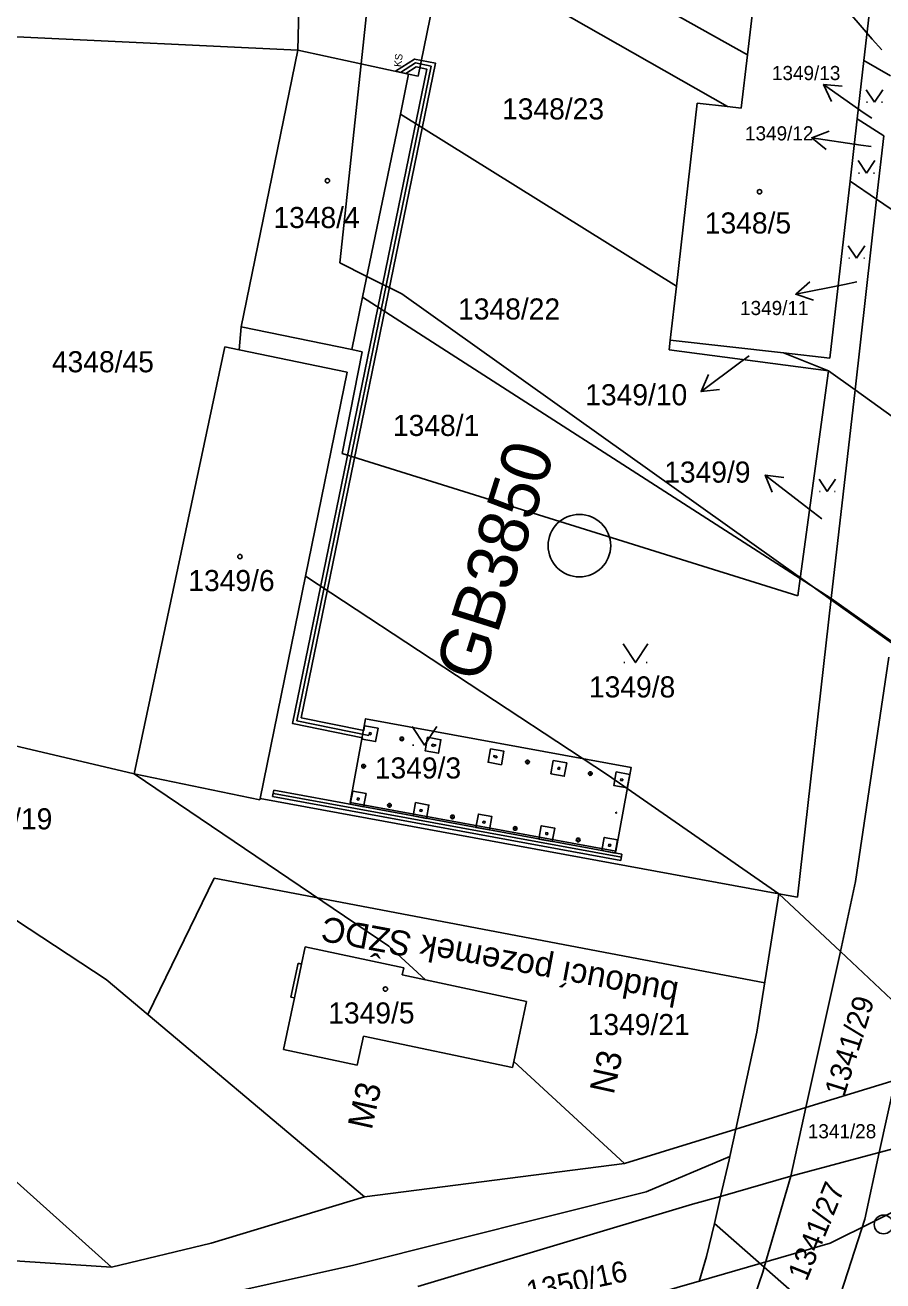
# Model space of a CAD drawing. Extents: x -735036 to -734743, y -1144813 to -1144181.
# Drawn here: x -734915.4 to -734846.3, y -1144707.5 to -1144606.3 of the extents above; entities that cross this region are included whole.
import ezdxf

# ---------------------------------------------------------------- set-up
doc = ezdxf.new("R2010")
doc.units = 0
for name, color, linetype in [('A3_ODVODŇOVACÍ ŽLAB', 7, 'Continuous'), ('A3_SIT_OBJEKT_N', 7, 'Continuous'), ('A3_SIT_OBJEKTY_N01', 7, 'Continuous'), ('BPEJ', 7, 'Continuous'), ('CKEL_VEDENI_NN_PODZ_N', 7, 'Continuous'), ('CKTEXTY_MALE', 7, 'Continuous'), ('hranice pl. určené SŽDC', 7, 'Continuous'), ('Katastr_HRANICE DRÁHY', 7, 'Continuous'), ('Katastr_Hranice parcel', 7, 'Continuous'), ('Katastr_Parcelní čísla', 7, 'Continuous'), ('Katastr_Slučkované čáry', 7, 'Continuous'), ('Katastr_Značky kultur', 7, 'Continuous'), ('ŽBP', 7, 'Continuous')]:
    doc.layers.add(name, color=color, linetype=linetype)

msp = doc.modelspace()

# ---------------------------------------------------------------- linework, layer by layer
at = {"layer": 'A3_ODVODŇOVACÍ ŽLAB'}
msp.add_line((-734867.33, -1144673.4), (-734895.36, -1144668.25), dxfattribs=at)
at = {"layer": 'A3_SIT_OBJEKT_N'}
for p, q in [((-734895.42, -1144668.49), (-734895.31, -1144668)), ((-734867.38, -1144673.65), (-734895.42, -1144668.49)), ((-734895.31, -1144668), (-734867.29, -1144673.15)), ((-734867.29, -1144673.15), (-734867.38, -1144673.65))]:
    msp.add_line(p, q, dxfattribs=at)
at = {"layer": 'A3_SIT_OBJEKTY_N01'}
for p, q in [((-734887.65, -1144663.5), (-734887.62, -1144663.35)), ((-734887.5, -1144663.53), (-734887.65, -1144663.5)), ((-734887.62, -1144663.35), (-734887.48, -1144663.38)), ((-734887.48, -1144663.38), (-734887.5, -1144663.53)), ((-734885.06, -1144663.88), (-734885.05, -1144663.83)), ((-734885, -1144663.9), (-734885.06, -1144663.88)), ((-734885.05, -1144663.83), (-734884.99, -1144663.84)), ((-734884.99, -1144663.84), (-734885, -1144663.9)), ((-734882.59, -1144664.43), (-734882.56, -1144664.28)), ((-734882.44, -1144664.46), (-734882.59, -1144664.43)), ((-734882.56, -1144664.28), (-734882.31, -1144664.33)), ((-734882.43, -1144664.41), (-734882.44, -1144664.46)), ((-734882.33, -1144664.43), (-734882.43, -1144664.41)), ((-734882.31, -1144664.33), (-734882.33, -1144664.43)), ((-734877.61, -1144665.29), (-734877.59, -1144665.2)), ((-734877.51, -1144665.31), (-734877.61, -1144665.29)), ((-734877.59, -1144665.2), (-734877.35, -1144665.24)), ((-734877.52, -1144665.36), (-734877.51, -1144665.31)), ((-734877.37, -1144665.39), (-734877.52, -1144665.36)), ((-734877.35, -1144665.24), (-734877.37, -1144665.39)), ((-734874.93, -1144665.75), (-734874.92, -1144665.69)), ((-734874.92, -1144665.69), (-734874.86, -1144665.7)), ((-734874.86, -1144665.7), (-734874.87, -1144665.76)), ((-734888.13, -1144666.09), (-734888.12, -1144666.03)), ((-734888.07, -1144666.1), (-734888.13, -1144666.09)), ((-734888.12, -1144666.03), (-734888.06, -1144666.04)), ((-734888.06, -1144666.04), (-734888.07, -1144666.1)), ((-734874.87, -1144665.76), (-734874.93, -1144665.75)), ((-734872.46, -1144666.29), (-734872.43, -1144666.15)), ((-734872.31, -1144666.32), (-734872.46, -1144666.29)), ((-734872.43, -1144666.15), (-734872.28, -1144666.17)), ((-734872.28, -1144666.17), (-734872.31, -1144666.32)), ((-734869.86, -1144666.68), (-734869.85, -1144666.62)), ((-734869.8, -1144666.69), (-734869.86, -1144666.68)), ((-734869.85, -1144666.62), (-734869.79, -1144666.63)), ((-734869.79, -1144666.63), (-734869.8, -1144666.69)), ((-734867.39, -1144667.22), (-734867.36, -1144667.08)), ((-734867.24, -1144667.25), (-734867.39, -1144667.22)), ((-734867.36, -1144667.08), (-734867.22, -1144667.1)), ((-734867.22, -1144667.1), (-734867.24, -1144667.25)), ((-734888.62, -1144668.76), (-734888.59, -1144668.61)), ((-734888.59, -1144668.61), (-734888.44, -1144668.64)), ((-734888.44, -1144668.64), (-734888.47, -1144668.79)), ((-734888.47, -1144668.79), (-734888.62, -1144668.76)), ((-734886.04, -1144669.24), (-734886.03, -1144669.18)), ((-734885.98, -1144669.25), (-734886.04, -1144669.24)), ((-734886.03, -1144669.18), (-734885.97, -1144669.19)), ((-734885.97, -1144669.19), (-734885.98, -1144669.25)), ((-734883.55, -1144669.69), (-734883.53, -1144669.55)), ((-734883.41, -1144669.72), (-734883.55, -1144669.69)), ((-734883.53, -1144669.55), (-734883.38, -1144669.57)), ((-734883.38, -1144669.57), (-734883.41, -1144669.72)), ((-734880.98, -1144670.17), (-734880.97, -1144670.11)), ((-734880.92, -1144670.18), (-734880.98, -1144670.17)), ((-734880.97, -1144670.11), (-734880.91, -1144670.12)), ((-734880.91, -1144670.12), (-734880.92, -1144670.18)), ((-734878.49, -1144670.62), (-734878.46, -1144670.48)), ((-734878.34, -1144670.65), (-734878.49, -1144670.62)), ((-734878.46, -1144670.48), (-734878.31, -1144670.5)), ((-734878.31, -1144670.5), (-734878.34, -1144670.65)), ((-734867.78, -1144669.83), (-734867.77, -1144669.77)), ((-734867.72, -1144669.84), (-734867.78, -1144669.83)), ((-734867.77, -1144669.77), (-734867.71, -1144669.78)), ((-734867.71, -1144669.78), (-734867.72, -1144669.84)), ((-734875.91, -1144671.1), (-734875.9, -1144671.04)), ((-734875.85, -1144671.11), (-734875.91, -1144671.1)), ((-734875.9, -1144671.04), (-734875.84, -1144671.05)), ((-734875.84, -1144671.05), (-734875.85, -1144671.11)), ((-734873.42, -1144671.56), (-734873.4, -1144671.41)), ((-734873.28, -1144671.58), (-734873.42, -1144671.56)), ((-734873.4, -1144671.41), (-734873.25, -1144671.43)), ((-734873.25, -1144671.43), (-734873.28, -1144671.58)), ((-734870.85, -1144672.03), (-734870.84, -1144671.97)), ((-734870.79, -1144672.04), (-734870.85, -1144672.03)), ((-734870.84, -1144671.97), (-734870.78, -1144671.98)), ((-734870.78, -1144671.98), (-734870.79, -1144672.04)), ((-734868.36, -1144672.49), (-734868.33, -1144672.34)), ((-734868.21, -1144672.51), (-734868.36, -1144672.49)), ((-734868.33, -1144672.34), (-734868.18, -1144672.37)), ((-734868.18, -1144672.37), (-734868.21, -1144672.51))]:
    msp.add_line(p, q, dxfattribs=at)
for points in [[(-734888.19, -1144663.78), (-734888.21, -1144663.88), (-734887.12, -1144664.08), (-734886.92, -1144663), (-734888.01, -1144662.8), (-734888.08, -1144663.19), (-734893.11, -1144662.16), (-734882.3, -1144609.42), (-734883.98, -1144609.08), (-734885.53, -1144610.07), (-734884.7, -1144610.25), (-734883.87, -1144609.71), (-734883.01, -1144609.89), (-734893.81, -1144662.63)], [(-734889.17, -1144668.97), (-734887.93, -1144662.23), (-734866.54, -1144666.16), (-734867.77, -1144672.9)], [(-734882.94, -1144663.73), (-734883.14, -1144664.81), (-734882.06, -1144665.01), (-734881.86, -1144663.93)], [(-734877.88, -1144664.66), (-734878.07, -1144665.74), (-734876.99, -1144665.94), (-734876.79, -1144664.86)], [(-734872.81, -1144665.59), (-734873.01, -1144666.67), (-734871.93, -1144666.87), (-734871.73, -1144665.79)], [(-734867.75, -1144666.52), (-734867.94, -1144667.61), (-734866.86, -1144667.8), (-734866.66, -1144666.72)], [(-734889.17, -1144669.13), (-734888.97, -1144668.06), (-734887.89, -1144668.26), (-734888.09, -1144669.33)], [(-734884.11, -1144670.06), (-734883.91, -1144668.99), (-734882.83, -1144669.19), (-734883.02, -1144670.26)], [(-734879.04, -1144670.99), (-734878.84, -1144669.92), (-734877.76, -1144670.12), (-734877.96, -1144671.19)], [(-734873.98, -1144671.93), (-734873.78, -1144670.85), (-734872.7, -1144671.05), (-734872.89, -1144672.12)], [(-734868.91, -1144672.86), (-734868.71, -1144671.79), (-734867.63, -1144671.98), (-734867.83, -1144673.06)]]:
    msp.add_lwpolyline(points, close=True, dxfattribs=at)
for centre in [(-734885.02, -1144663.86), (-734874.89, -1144665.72), (-734888.09, -1144666.06), (-734869.83, -1144666.65), (-734886.01, -1144669.21), (-734880.94, -1144670.14), (-734875.88, -1144671.07), (-734870.81, -1144672)]:
    msp.add_circle(centre, 0.15, dxfattribs=at)
at = {"layer": 'BPEJ'}
for points in [[(-734886.95, -1144596.85), (-734888.29, -1144609.47), (-734890, -1144625.5), (-734887.82, -1144626.59), (-734885, -1144628), (-734852.91, -1144650.88), (-734852.15, -1144651.42), (-734850.43, -1144652.65), (-734834.73, -1144663.85), (-734834.99, -1144666), (-734826.29, -1144672.48), (-734825.67, -1144670.31), (-734820.68, -1144673.87), (-734820.5, -1144674), (-734820.82, -1144674.78), (-734818.52, -1144675.9), (-734816.23, -1144677.02), (-734810.97, -1144679.57), (-734807.09, -1144681.45), (-734806.63, -1144681.68), (-734805.5, -1144680.5), (-734802.5, -1144683.25), (-734799.5, -1144686)], [(-734875.41, -1144811.46), (-734872.9, -1144805.78), (-734867.89, -1144794.43), (-734854.34, -1144763.72), (-734850.2, -1144754.32), (-734842.33, -1144736.48), (-734836.55, -1144723.38), (-734836.47, -1144723.21), (-734828.55, -1144705.26), (-734828.47, -1144705.07), (-734837.14, -1144702.69), (-734834.01, -1144696), (-734841.2, -1144699.67), (-734841.55, -1144701.48), (-734843.42, -1144700.96), (-734850.5, -1144704.5), (-734856.16, -1144706.13), (-734861.05, -1144707.56), (-734878.02, -1144712.44), (-734888.06, -1144715.34), (-734896.33, -1144716.95), (-734914.06, -1144720.39), (-734915.89, -1144720.74)]]:
    msp.add_lwpolyline(points, dxfattribs=at)
at = {"layer": 'CKEL_VEDENI_NN_PODZ_N'}
msp.add_lwpolyline([(-734885.11, -1144610.16), (-734883.92, -1144609.39), (-734882.65, -1144609.66), (-734893.46, -1144662.4), (-734887.67, -1144663.58)], dxfattribs=at)
at = {"layer": 'hranice pl. určené SŽDC'}
for p, q in [((-734905.48, -1144686.06), (-734900.12, -1144675.07)), ((-734900.12, -1144675.07), (-734855.78, -1144683.52))]:
    msp.add_line(p, q, dxfattribs=at)
at = {"layer": 'Katastr_HRANICE DRÁHY'}
for p, q in [((-734847.02, -1144618.27), (-734846.95, -1144618.27)), ((-734906.57, -1144666.66), (-734899.28, -1144632.27)), ((-734906.57, -1144666.66), (-734930.18, -1144661.14)), ((-734867.09, -1144698.06), (-734888.03, -1144700.76))]:
    msp.add_line(p, q, dxfattribs=at)
for points in [[(-734893.32, -1144605), (-734893.39, -1144608.37)], [(-734896.4, -1144623.07), (-734893.39, -1144608.37)], [(-734846.19, -1144615.27), (-734846.77, -1144620.37)], [(-734846.77, -1144620.37), (-734848.51, -1144635.73)], [(-734897.96, -1144630.65), (-734896.4, -1144623.07)], [(-734897.96, -1144630.65), (-734898.12, -1144632.51)], [(-734899.28, -1144632.27), (-734898.12, -1144632.51)], [(-734848.51, -1144635.73), (-734850.42, -1144652.54)], [(-734850.42, -1144652.54), (-734853.15, -1144676.61)], [(-734908.82, -1144683.24), (-734932.55, -1144667.65)], [(-734854.65, -1144676.33), (-734856.41, -1144687.5)], [(-734853.15, -1144676.61), (-734854.65, -1144676.33)], [(-734888.03, -1144700.76), (-734908.82, -1144683.24)], [(-734856.41, -1144687.5), (-734858.12, -1144695.3)], [(-734867.09, -1144698.06), (-734858.12, -1144695.3)]]:
    msp.add_lwpolyline(points, dxfattribs=at)
at = {"layer": 'Katastr_Hranice parcel'}
for points in [[(-734857.17, -1144608.74), (-734880.66, -1144595.58)], [(-734883.7, -1144610.47), (-734881.55, -1144599.93)], [(-734881.55, -1144599.93), (-734858.79, -1144612.91)], [(-734846.8, -1144600.6), (-734847.79, -1144609.19)], [(-734856.63, -1144604.15), (-734857.17, -1144608.74)], [(-734916.03, -1144607.28), (-734893.39, -1144608.37)], [(-734893.39, -1144608.37), (-734884.47, -1144610.3)], [(-734857.17, -1144608.74), (-734857.68, -1144613.04)], [(-734847.79, -1144609.19), (-734848.33, -1144613.91)], [(-734845.64, -1144610.44), (-734847.79, -1144609.19)], [(-734885.13, -1144613.52), (-734884.47, -1144610.3)], [(-734884.47, -1144610.3), (-734883.7, -1144610.47)], [(-734862.9, -1144627.38), (-734861.22, -1144612.64)], [(-734858.79, -1144612.91), (-734861.22, -1144612.64)], [(-734857.68, -1144613.04), (-734858.79, -1144612.91)], [(-734888.17, -1144628.27), (-734885.13, -1144613.52)], [(-734885.13, -1144613.52), (-734862.9, -1144627.38)], [(-734848.33, -1144613.91), (-734848.9, -1144618.91)], [(-734848.33, -1144613.91), (-734846.19, -1144615.27)], [(-734848.9, -1144618.91), (-734850.53, -1144633.19)], [(-734848.9, -1144618.91), (-734846.77, -1144620.37)], [(-734846.77, -1144620.37), (-734841.89, -1144623.71)], [(-734889.04, -1144632.49), (-734888.17, -1144628.27)], [(-734888.17, -1144628.27), (-734852.92, -1144650.93)], [(-734863.4, -1144631.72), (-734862.9, -1144627.38)], [(-734889.04, -1144632.49), (-734897.96, -1144630.65)], [(-734863.4, -1144631.72), (-734863.49, -1144632.52)], [(-734854.28, -1144632.76), (-734863.4, -1144631.72)], [(-734898.12, -1144632.51), (-734889.41, -1144634.32)], [(-734889.81, -1144640.87), (-734888.21, -1144632.66)], [(-734888.21, -1144632.66), (-734889.04, -1144632.49)], [(-734850.65, -1144634.19), (-734863.49, -1144632.52)], [(-734850.53, -1144633.19), (-734854.28, -1144632.76)], [(-734850.65, -1144634.19), (-734854.28, -1144632.76)], [(-734889.41, -1144634.32), (-734892.76, -1144650.74)], [(-734852.92, -1144650.93), (-734850.65, -1144634.19)], [(-734848.51, -1144635.73), (-734850.65, -1144634.19)], [(-734843.69, -1144639.2), (-734848.51, -1144635.73)], [(-734853.11, -1144652.34), (-734889.81, -1144640.87)], [(-734892.76, -1144650.74), (-734896.42, -1144668.65)], [(-734892.76, -1144650.74), (-734868.44, -1144666.76)], [(-734852.92, -1144650.93), (-734853.11, -1144652.34)], [(-734852.92, -1144650.93), (-734850.42, -1144652.54)], [(-734850.42, -1144652.54), (-734845.63, -1144655.97)], [(-734896.45, -1144668.76), (-734906.57, -1144666.66)], [(-734906.57, -1144666.66), (-734886.07, -1144680.55)], [(-734854.65, -1144676.33), (-734868.44, -1144666.76)], [(-734896.42, -1144668.65), (-734896.45, -1144668.76)], [(-734854.65, -1144676.33), (-734896.42, -1144668.65)], [(-734849.69, -1144680.98), (-734854.65, -1144676.33)], [(-734892.81, -1144680.6), (-734893.1, -1144682)], [(-734884.85, -1144682.29), (-734892.81, -1144680.6)], [(-734886.07, -1144680.55), (-734883.11, -1144683.28)], [(-734844.19, -1144686.14), (-734849.69, -1144680.98)], [(-734908.39, -1144706.42), (-734935.61, -1144682)], [(-734893.37, -1144681.94), (-734893.96, -1144684.67)], [(-734893.1, -1144682), (-734893.37, -1144681.94)], [(-734884.98, -1144682.88), (-734884.85, -1144682.29)], [(-734883.11, -1144683.28), (-734884.98, -1144682.88)], [(-734874.98, -1144685.01), (-734883.11, -1144683.28)], [(-734893.67, -1144684.73), (-734894.55, -1144688.88)], [(-734893.96, -1144684.67), (-734893.67, -1144684.73)], [(-734876, -1144689.84), (-734874.98, -1144685.01)], [(-734888.61, -1144690.15), (-734888.09, -1144687.8)], [(-734888.09, -1144687.8), (-734876.11, -1144690.34)], [(-734894.55, -1144688.88), (-734888.61, -1144690.15)], [(-734876.11, -1144690.34), (-734876, -1144689.84)], [(-734876, -1144689.84), (-734867.09, -1144698.06)], [(-734852.46, -1144693.56), (-734845.28, -1144691.36)], [(-734858.12, -1144695.3), (-734852.46, -1144693.56)], [(-734858.12, -1144695.3), (-734858.6, -1144697.51)], [(-734840.41, -1144695.55), (-734846.56, -1144697.19)], [(-734858.6, -1144697.51), (-734865.34, -1144700.35)], [(-734859.34, -1144700.73), (-734858.65, -1144697.78)], [(-734858.65, -1144697.78), (-734858.6, -1144697.51)], [(-734846.56, -1144697.19), (-734853.68, -1144699.09)], [(-734853.68, -1144699.09), (-734859.34, -1144700.73)], [(-734888.03, -1144700.76), (-734900.37, -1144704.49)], [(-734865.34, -1144700.35), (-734888.87, -1144706.25)], [(-734859.34, -1144700.73), (-734861.61, -1144701.35)], [(-734859.84, -1144702.9), (-734859.34, -1144700.73)], [(-734883.72, -1144707.99), (-734861.61, -1144701.35)], [(-734860.46, -1144705.55), (-734859.84, -1144702.9)], [(-734859.84, -1144702.9), (-734855.82, -1144706.43)], [(-734908.39, -1144706.42), (-734927.72, -1144705.17)], [(-734900.37, -1144704.49), (-734908.39, -1144706.42)], [(-734861.06, -1144707.58), (-734860.46, -1144705.55)], [(-734888.87, -1144706.25), (-734902.35, -1144709.26)], [(-734855.82, -1144706.43), (-734850.48, -1144711.13)]]:
    msp.add_lwpolyline(points, dxfattribs=at)
at = {"layer": 'Katastr_Parcelní čísla'}
for p, q in [((-734846.36, -1144608.35), (-734847.12, -1144607.47)), ((-734850.4, -1144612.5), (-734851.04, -1144611.14)), ((-734847.15, -1144613.85), (-734847.76, -1144613.43)), ((-734850.82, -1144616.36), (-734852, -1144615.43)), ((-734847.22, -1144616.14), (-734848.04, -1144616.02)), ((-734848.37, -1144627.04), (-734849.36, -1144627.24)), ((-734851.86, -1144628.51), (-734853.28, -1144628.03)), ((-734857.03, -1144632.99), (-734857.7, -1144633.49)), ((-734859.42, -1144635.71), (-734860.91, -1144635.88)), ((-734855.17, -1144643.99), (-734855.74, -1144642.6)), ((-734851.17, -1144646.14), (-734852.58, -1144645.05))]:
    msp.add_line(p, q, dxfattribs=at)
for points in [[(-734847.12, -1144607.47), (-734849.73, -1144604.44), (-734848.32, -1144604.94)], [(-734847.76, -1144613.43), (-734851.04, -1144611.14), (-734849.55, -1144611.27)], [(-734848.04, -1144616.02), (-734852, -1144615.43), (-734850.6, -1144614.88)], [(-734849.36, -1144627.24), (-734853.28, -1144628.03), (-734852.15, -1144627.04)], [(-734857.7, -1144633.49), (-734860.91, -1144635.88), (-734860.31, -1144634.5)], [(-734852.58, -1144645.05), (-734855.74, -1144642.6), (-734854.25, -1144642.8)]]:
    msp.add_lwpolyline(points, dxfattribs=at)
at = {"layer": 'Katastr_Slučkované čáry'}
for points in [[(-734848.46, -1144675.36), (-734845.78, -1144657.26)], [(-734849.69, -1144680.98), (-734848.46, -1144675.36)], [(-734852.46, -1144693.56), (-734849.69, -1144680.98)], [(-734893.1, -1144682), (-734893.67, -1144684.73)], [(-734845.28, -1144691.36), (-734846.56, -1144697.19)], [(-734853.68, -1144699.09), (-734852.46, -1144693.56)], [(-734846.56, -1144697.19), (-734847.73, -1144702.54)], [(-734855.82, -1144706.43), (-734853.68, -1144699.09)], [(-734847.73, -1144702.54), (-734850.48, -1144711.13)], [(-734859.82, -1144718.19), (-734855.94, -1144706.83)], [(-734855.94, -1144706.83), (-734855.82, -1144706.43)]]:
    msp.add_lwpolyline(points, dxfattribs=at)
at = {"layer": 'Katastr_Značky kultur'}
for p, q in [((-734847.61, -1144611.55), (-734846.94, -1144612.55)), ((-734846.94, -1144612.55), (-734846.27, -1144611.55)), ((-734847.58, -1144612.55), (-734847.51, -1144612.55)), ((-734846.37, -1144612.55), (-734846.3, -1144612.55)), ((-734848.26, -1144617.27), (-734847.59, -1144618.27)), ((-734847.59, -1144618.27), (-734846.92, -1144617.27)), ((-734848.23, -1144618.27), (-734848.16, -1144618.27)), ((-734849.05, -1144624.13), (-734848.38, -1144625.13)), ((-734848.38, -1144625.13), (-734847.71, -1144624.13)), ((-734849.02, -1144625.13), (-734848.95, -1144625.13)), ((-734847.81, -1144625.13), (-734847.74, -1144625.13)), ((-734851.41, -1144642.93), (-734850.74, -1144643.93)), ((-734850.74, -1144643.93), (-734850.07, -1144642.93)), ((-734851.38, -1144643.93), (-734851.31, -1144643.93)), ((-734850.17, -1144643.93), (-734850.1, -1144643.93)), ((-734867.14, -1144657.71), (-734867.04, -1144657.71)), ((-734865.34, -1144657.71), (-734865.24, -1144657.71)), ((-734884.14, -1144664.35), (-734884.04, -1144664.35)), ((-734882.34, -1144664.35), (-734882.24, -1144664.35))]:
    msp.add_line(p, q, dxfattribs=at)
for points in [[(-734867.19, -1144656.21), (-734866.19, -1144657.71), (-734865.19, -1144656.21)], [(-734884.19, -1144662.85), (-734883.19, -1144664.35), (-734882.19, -1144662.85)]]:
    msp.add_lwpolyline(points, dxfattribs=at)
for centre, radius in [((-734891.01, -1144618.89), 0.175), ((-734856.2, -1144619.77), 0.175), ((-734898.05, -1144649.17), 0.175), ((-734886.34, -1144684.01), 0.175), ((-734846.21, -1144702.98), 0.756)]:
    msp.add_circle(centre, radius, dxfattribs=at)
at = {"layer": 'ŽBP'}
msp.add_circle((-734870.71, -1144648.29), 2.52, dxfattribs=at)

# ---------------------------------------------------------------- texts
at = {"layer": 'CKTEXTY_MALE'}
msp.add_text('KS', height=0.6, rotation=83.326, dxfattribs=at).set_placement((-734885.06, -1144609.75))
at = {"layer": 'hranice pl. určené SŽDC'}
for s, rotation, p in [('budoucí pozemek SŽDC', 169.4202, (-734862.62, -1144683.49)), ('N3', 77.5575, (-734867.95, -1144692.57)), ('M3', 77.5575, (-734887.44, -1144695.42))]:
    msp.add_text(s, height=2, rotation=rotation, dxfattribs=at).set_placement(p)
at = {"layer": 'Katastr_Parcelní čísla'}
for s, height, p in [('1349/13', 1.14, (-734855.2, -1144610.78)), ('1348/23', 1.7, (-734876.94, -1144613.95)), ('1349/12', 1.14, (-734857.37, -1144615.64)), ('1348/4', 1.7, (-734895.36, -1144622.7)), ('1348/5', 1.7, (-734860.61, -1144623.14)), ('1348/22', 1.7, (-734880.48, -1144630.07)), ('1349/11', 1.14, (-734857.77, -1144629.71)), ('4348/45', 1.7, (-734913.2, -1144634.32)), ('1349/10', 1.7, (-734870.24, -1144636.98)), ('1348/1', 1.7, (-734885.73, -1144639.45)), ('1349/9', 1.7, (-734863.88, -1144643.21)), ('1349/6', 1.7, (-734902.21, -1144651.95)), ('1349/8', 1.7, (-734869.94, -1144660.52)), ('1349/3', 1.7, (-734887.19, -1144667.05)), ('1349/19', 1.7, (-734921.38, -1144671.15)), ('1349/5', 1.7, (-734890.94, -1144686.79)), ('1349/21', 1.7, (-734870.04, -1144687.72)), ('1341/28', 1.14, (-734852.31, -1144696.04))]:
    msp.add_text(s, height=height, dxfattribs=at).set_placement(p)
for s, rotation, p in [('1341/29', 72.6424, (-734849.38, -1144692.76)), ('1341/27', 67.7765, (-734852.41, -1144707.63)), ('1350/16', 11.9909, (-734874.77, -1144709.23))]:
    msp.add_text(s, height=1.7, rotation=rotation, dxfattribs=at).set_placement(p)
at = {"layer": 'ŽBP'}
msp.add_text('GB3850', height=4, rotation=72.4954, dxfattribs=at).set_placement((-734878.57, -1144659.45))

doc.saveas('drawing.dxf')
